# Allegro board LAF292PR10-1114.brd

Outline 301 x 98 mm; copper layers: TOP, GND1, IN1, GND2, IN2, GND3, VCC, IN3, GND4, IN4, GND5, BOTTOM. Coordinates in mm from the lower left corner of the outline.

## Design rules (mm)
net group CLK_ITPXDP_: nets CLK_ITPXDP_N CLK_ITPXDP_P
net group CLK_ITPXDP__R: nets CLK_ITPXDP_N_R CLK_ITPXDP_P_R
net group CPU_DP1_0: nets CPU_DP1_N0 CPU_DP1_P0
net group CPU_DP1_0_C: nets CPU_DP1_N0_C CPU_DP1_P0_C
net group CPU_DP1_1: nets CPU_DP1_N1 CPU_DP1_P1
net group CPU_DP1_1_C: nets CPU_DP1_N1_C CPU_DP1_P1_C
net group CPU_DP1_2: nets CPU_DP1_N2 CPU_DP1_P2
net group CPU_DP1_2_C: nets CPU_DP1_N2_C CPU_DP1_P2_C
net group CPU_DP1_3: nets CPU_DP1_N3 CPU_DP1_P3
net group CPU_DP1_3_C: nets CPU_DP1_N3_C CPU_DP1_P3_C
net group CPU_DP1_AUX: nets CPU_DP1_AUXN CPU_DP1_AUXP
net group CPU_DP1_AUX_C: nets CPU_DP1_AUXN_C CPU_DP1_AUXP_C
net group CPU_DP2_0: nets CPU_DP2_N0 CPU_DP2_P0
net group CPU_DP2_0_C: nets CPU_DP2_N0_C CPU_DP2_P0_C
net group CPU_DP2_1: nets CPU_DP2_N1 CPU_DP2_P1
net group CPU_DP2_1_C: nets CPU_DP2_N1_C CPU_DP2_P1_C
net group CPU_DP2_2: nets CPU_DP2_N2 CPU_DP2_P2
net group CPU_DP2_2_C: nets CPU_DP2_N2_C CPU_DP2_P2_C
net group CPU_DP2_3: nets CPU_DP2_N3 CPU_DP2_P3
net group CPU_DP2_3_C: nets CPU_DP2_N3_C CPU_DP2_P3_C
net group CPU_DP2_AUX: nets CPU_DP2_AUXN CPU_DP2_AUXP
net group CPU_DP2_AUX_C: nets CPU_DP2_AUXN_C CPU_DP2_AUXP_C
net group CPU_DP3_AUX: nets CPU_DP3_AUXN CPU_DP3_AUXP
net group DP_GT_SENSE: nets VCC_GT_SENSE VSS_GT_SENSE
net group EDP_AUX: nets EDP_AUXN EDP_AUXP
net group EDP_TX0: nets EDP_TXN0 EDP_TXP0
net group EDP_TX1: nets EDP_TXN1 EDP_TXP1
net group EDP_TX2: nets EDP_TXN2 EDP_TXP2
net group EDP_TX3: nets EDP_TXN3 EDP_TXP3
net group HDA-30: nets HDA_BIT_CLK HDA_BIT_CLK_R
net group HDMI_CLK: nets HDMI_CLKN HDMI_CLKP
net group HDMI_L_CLK: nets HDMI_L_CLKN HDMI_L_CLKP
net group HDMI_L_TX_0: nets HDMI_L_TX_N0 HDMI_L_TX_P0
net group HDMI_L_TX_1: nets HDMI_L_TX_N1 HDMI_L_TX_P1
net group HDMI_L_TX_2: nets HDMI_L_TX_N2 HDMI_L_TX_P2
net group HDMI_TX_0: nets HDMI_TX_N0 HDMI_TX_P0
net group HDMI_TX_1: nets HDMI_TX_N1 HDMI_TX_P1
net group HDMI_TX_2: nets HDMI_TX_N2 HDMI_TX_P2
net group INT_SPK_L: nets INT_SPK_L+ INT_SPK_L-
net group INT_SPK_R: nets INT_SPK_R+ INT_SPK_R-
net group INT_SPKR_L: nets INT_SPKR_L+ INT_SPKR_L-
net group INT_SPKR_R: nets INT_SPKR_R+ INT_SPKR_R-
net group PCIE_PRX_DTX_5: nets PCIE_PRX_DTX_N5 PCIE_PRX_DTX_P5
net group PCIE_PRX_DTX_7: nets PCIE_PRX_DTX_N7 PCIE_PRX_DTX_P7
net group PCIE_PRX_DTX_8: nets PCIE_PRX_DTX_N8 PCIE_PRX_DTX_P8
net group PCIE_PRX_DTX_9: nets PCIE_PRX_DTX_N9 PCIE_PRX_DTX_P9
net group PCIE_PRX_DTX_10: nets PCIE_PRX_DTX_N10 PCIE_PRX_DTX_P10
net group PCIE_PRX_DTX_11: nets PCIE_PRX_DTX_N11 PCIE_PRX_DTX_P11
net group PCIE_PRX_DTX_12: nets PCIE_PRX_DTX_N12 PCIE_PRX_DTX_P12
net group PCIE_PRX_L_DTX_7: nets PCIE_PRX_L_DTX_N7 PCIE_PRX_L_DTX_P7
net group PCIE_PRX_SW_DTX_7: nets PCIE_PRX_SW_DTX_N7 PCIE_PRX_SW_DTX_P7
net group PCIE_PTX_DRX_5: nets PCIE_PTX_DRX_N5 PCIE_PTX_DRX_P5
net group PCIE_PTX_DRX_7: nets PCIE_PTX_DRX_N7 PCIE_PTX_DRX_P7
net group PCIE_PTX_DRX_8: nets PCIE_PTX_DRX_N8 PCIE_PTX_DRX_P8
net group PCIE_PTX_DRX_9: nets PCIE_PTX_DRX_N9 PCIE_PTX_DRX_P9
net group PCIE_PTX_DRX_10: nets PCIE_PTX_DRX_N10 PCIE_PTX_DRX_P10
net group PCIE_PTX_DRX_11: nets PCIE_PTX_DRX_N11 PCIE_PTX_DRX_P11
net group PCIE_PTX_DRX_12: nets PCIE_PTX_DRX_N12 PCIE_PTX_DRX_P12
net group PCIE_PTX_L_DRX_7: nets PCIE_PTX_L_DRX_N7 PCIE_PTX_L_DRX_P7
net group REM_DIODE1: nets REM_DIODE1_N REM_DIODE1_P
net group SD/MMCDAT0/RCLK+: nets SD/MMCDAT0/RCLK+ SD/MMCDAT1/RCLK-
net group SD/MMCDAT0/RCLK+-R: nets SD/MMCDAT0/RCLK+_R SD/MMCDAT1/RCLK-_R
net group SD_UHS2_D0: nets SD_UHS2_D0N SD_UHS2_D0P
net group SD_UHS2_D1: nets SD_UHS2_D1N SD_UHS2_D1P
net group TBTA_AUX: nets TBTA_AUXN TBTA_AUXP
net group TBTA_AUX_C: nets TBTA_AUXN_C TBTA_AUXP_C
net group TBTA_BOT_: nets TBTA_BOT_N TBTA_BOT_P
net group TBTA_BOT__R: nets TBTA_BOT_N_R TBTA_BOT_P_R
net group TBTA_TOP_: nets TBTA_TOP_N TBTA_TOP_P
net group TBTA_TOP__R: nets TBTA_TOP_N_R TBTA_TOP_P_R
net group TBTA_USB20_: nets TBTA_USB20_N TBTA_USB20_P
net group TBTB_AUX: nets TBTB_AUXN TBTB_AUXP
net group TBTB_AUX_C: nets TBTB_AUXN_C TBTB_AUXP_C
net group TBTB_BOT_: nets TBTB_BOT_N TBTB_BOT_P
net group TBTB_BOT__R: nets TBTB_BOT_N_R TBTB_BOT_P_R
net group TBTB_TOP_: nets TBTB_TOP_N TBTB_TOP_P
net group TBTB_TOP__R: nets TBTB_TOP_N_R TBTB_TOP_P_R
net group TBTB_USB20_: nets TBTB_USB20_N TBTB_USB20_P
net group USB2.0-3: nets USB20_N3 USB20_P3
net group USB3_PRX_C_DTX_N4: nets USB3_PRX_C_DTX_N4 USB3_PRX_DTX_N4
net group USB3_PRX_C_DTX_P4: nets USB3_PRX_C_DTX_P4 USB3_PRX_DTX_P4
net group USB3_PRX_DTX_1: nets USB3_PRX_DTX_N1 USB3_PRX_DTX_P1
net group USB3_PRX_DTX_2: nets USB3_PRX_DTX_N2 USB3_PRX_DTX_P2
net group USB3_PRX_DTX_3: nets USB3_PRX_DTX_N3 USB3_PRX_DTX_P3
net group USB3_PTX_C_DRX_1: nets USB3_PTX_C_DRX_N1 USB3_PTX_C_DRX_P1
net group USB3_PTX_C_DRX_2: nets USB3_PTX_C_DRX_N2 USB3_PTX_C_DRX_P2
net group USB3_PTX_C_DRX_3: nets USB3_PTX_C_DRX_N3 USB3_PTX_C_DRX_P3
net group USB3_PTX_C_DRX_4: nets USB3_PTX_C_DRX_N4 USB3_PTX_C_DRX_P4
net group USB3_PTX_DRX_1: nets USB3_PTX_DRX_N1 USB3_PTX_DRX_P1
net group USB3_PTX_DRX_2: nets USB3_PTX_DRX_N2 USB3_PTX_DRX_P2
net group USB3_PTX_DRX_3: nets USB3_PTX_DRX_N3 USB3_PTX_DRX_P3
net group USB3_PTX_DRX_4: nets USB3_PTX_DRX_N4 USB3_PTX_DRX_P4
net group USB20_1: nets USB20_N1 USB20_P1
net group USB20_2: nets USB20_N2 USB20_P2
net group USB20_2_R: nets USB20_N2_R USB20_P2_R
net group USB20_4: nets USB20_N4 USB20_P4
net group USB20_4_L: nets USB20_N4_L USB20_P4_L
net group USB20_5: nets USB20_N5 USB20_P5
net group USB20_5_R: nets USB20_N5_R USB20_P5_R
net group USB20_6: nets USB20_N6 USB20_P6
net group USB20_6_R: nets USB20_N6_R USB20_P6_R
net group USB20_7: nets USB20_N7 USB20_P7
net group USB20_7_L: nets USB20_N7_L USB20_P7_L
net group USB20_8: nets USB20_N8 USB20_P8
net group USB20_8_R: nets USB20_N8_R USB20_P8_R
net group USB20_10: nets USB20_N10 USB20_P10
net group W10S10: nets AUD_HP_NB_SENSE AUD_SENSE_A
net group 5: nets BC_DAT_ECE1117 CPU_DP1_CTRL_DATA CPU_DP2_CTRL_DATA DDR_XDP_WAN_SMBDAT ESPI_IO0 ESPI_IO0_R ESPI_IO1 ESPI_IO1_R ESPI_IO2 ESPI_IO2_R ESPI_IO3 ESPI_IO3_R I2C1_SDA_TP ISH_I2C0_SDA ISH_I2C1_SDA ISH_I2C2_SDA MEM_SMBDATA PBAT_SMBDAT_C PCH_SPI_CS#0 PCH_SPI_CS#0_R1 PCH_SPI_CS#0_R2 PCH_SPI_CS#1 PCH_SPI_CS#1_R1 PCH_SPI_CS#1_R2 PCH_SPI_CS#2 PCH_SPI_CS#2_R PCH_SPI_D0 PCH_SPI_D0_2_R PCH_SPI_D0_R1 PCH_SPI_D1 PCH_SPI_D1_2_R PCH_SPI_D1_R1 PCH_SPI_D2 PCH_SPI_D2_R1 PCH_SPI_D3 PCH_SPI_D3_R1 PCH_SPI_DO2_XDP PCH_SPI_DO_XDP SML0_SMBDATA SML1_SMBDATA TBT_I2C_SDA TBT_ROM_CS# TBT_ROM_DI TBT_ROM_DO UPD1_SMBDAT UPD1_SMBUS_DAT_Q UPD2_SMBDAT UPD2_SMBUS_DAT_Q
net group 10: nets AUD_HP_OUT_L AUD_HP_OUT_L1 AUD_HP_OUT_R AUD_HP_OUT_R1 BC_CLK_ECE1117 CFG0 CLK_TP_SIO_I2C_DAT CPU_DP1_CTRL_CLK CPU_DP2_CTRL_CLK DAT_TP_SIO_I2C_CLK DAT_TP_SIO_R DDR_XDP_WAN_SMBCLK ESPI_CLK H_CATERR# H_THERMTRIP# H_VCCST_PWRGD_XDP HDMI_CTRL_CLK INTRUDER# ISH_I2C0_SCL ISH_I2C1_SCL ISH_I2C2_SCL MEM_SMBCLK N39469972 PBAT_SMBCLK_C PCH_DPWROK PCH_PCIE_WAKE# PCH_PLTRST# PCH_PLTRST#_EC PCH_RSMRST# PCH_RTCRST# PCH_SPI_CLK PCH_SPI_CLK_2_R PCH_SPI_CLK_R1 PCIE_WAKE# PCIE_WAKE#_R PLTRST_TPM# RESET_OUT#_R SIO_PWRBTN# SML0_SMBCLK SML1_SMBCLK SRTCRST# SUSCLK_R SYS_RESET# SYS_RESET#_R TBT_I2C_SCL TBT_ROM_CLK TBTA_ROM_CLK_PD TS_I2C_SCL UPD1_SMBCLK UPD1_SMBUS_CLK_Q UPD2_SMBCLK UPD2_SMBUS_CLK_Q VCCST_PWRGD VCCST_PWRGD_CPU VCCST_PWRGD_EC XDP_OBS0 XDP_OBS0_R XDP_OBS1 XDP_OBS1_R
net group 12: nets CPU_XDP_TDI CPU_XDP_TDO CPU_XDP_TMS H_CPU_SVIDALRT# PCH_JTAG_TDI PCH_JTAG_TDO PCH_JTAG_TMS PCH_RSMRST#_AND PECI_EC PECI_EC_R SD/MMCCD# SD/MMCCLK SD/MMCCLK_R SD/MMCCMD SD/MMCDAT2 SD/MMCDAT2_R SD/MMCDAT3 SD/MMCDAT3_R SDWP TDI_XDP TDO_XDP VIDALERT_N VIDALERT_N_B VIDSCLK VIDSCLK_B VIDSOUT VIDSOUT_B XDP_JTAGX XDP_TMS
net group 15: nets PCH_RTCX2 PCH_RTCX2_R RTCRST_ON WIGIG_32KHZ
net group 20: nets CPU_XDP_TCLK MSCLK PCH_JTAG_TCK PCH_RTCX1 PCI_CLK_LPC1 SUSCLK XCLK_BIASREF XTAL_25_IN XTAL_25_OUT XTAL_25_OUT_R
net group 25: nets N28769860 VCCIO_SENSE VCCSENSE VSSIO_SENSE
net group 90H-TBT: nets TBTA_RX1N TBTA_RX1P TBTA_RX2N TBTA_RX2P TBTA_TX1N TBTA_TX1N_C TBTA_TX1P TBTA_TX1P_C TBTA_TX2N TBTA_TX2N_C TBTA_TX2P TBTA_TX2P_C TBTB_RX1N TBTB_RX1P TBTB_RX2N TBTB_RX2P TBTB_TX1N TBTB_TX1N_C TBTB_TX1P TBTB_TX1P_C TBTB_TX2N TBTB_TX2N_C TBTB_TX2P TBTB_TX2P_C
net group AR DP: nets TBTA_LSRX TBTA_LSRX_R TBTA_LSTX TBTA_LSTX_R TBTA_SBU1 TBTA_SBU1_R TBTA_SBU2 TBTA_SBU2_R TBTB_LSRX TBTB_LSRX_R TBTB_LSTX TBTB_LSTX_R TBTB_SBU1 TBTB_SBU1_R TBTB_SBU2 TBTB_SBU2_R
net group AR HDMI: nets AR_DP1_N0 AR_DP1_N1 AR_DP1_N2 AR_DP1_N3 AR_DP1_P0 AR_DP1_P1 AR_DP1_P2 AR_DP1_P3
net group ASYNCHRONOUS: nets +DDR_VREF_B_DQ CFG_RCOMP EDRAM_OPIO_RCOMP USBCOMP
net group CARD READER-RTS5250: nets SD/MMCCMD_R
net group CLK-PCIE-12-30: nets CLK_PCIE_N0 CLK_PCIE_N1 CLK_PCIE_N3 CLK_PCIE_N5 CLK_PCIE_P0 CLK_PCIE_P1 CLK_PCIE_P3 CLK_PCIE_P5
net group CODEC: nets HP_OUT_L HP_OUT_R LINE1_L LINE1_R
net group CONTROL LINK SIGNAL: nets PCH_CL_CLK1 PCH_CL_DATA1 PCH_CL_RST1#
net group DDRA_DQS0: nets DDR_A_D0 DDR_A_D1 DDR_A_D2 DDR_A_D3 DDR_A_D4 DDR_A_D5 DDR_A_D6 DDR_A_D7 DDR_A_DQS0 DDR_A_DQS#0
net group DDRA_DQS1: nets DDR_A_D8 DDR_A_D9 DDR_A_D10 DDR_A_D11 DDR_A_D12 DDR_A_D13 DDR_A_D14 DDR_A_D15 DDR_A_DQS1 DDR_A_DQS#1
net group DDRA_DQS2: nets DDR_A_D16 DDR_A_D17 DDR_A_D18 DDR_A_D19 DDR_A_D20 DDR_A_D21 DDR_A_D22 DDR_A_D23 DDR_A_DQS2 DDR_A_DQS#2
net group DDRA_DQS3: nets DDR_A_D24 DDR_A_D25 DDR_A_D26 DDR_A_D27 DDR_A_D28 DDR_A_D29 DDR_A_D30 DDR_A_D31 DDR_A_DQS3 DDR_A_DQS#3
net group DDRA_DQS4: nets DDR_A_D32 DDR_A_D33 DDR_A_D34 DDR_A_D35 DDR_A_D36 DDR_A_D37 DDR_A_D38 DDR_A_D39 DDR_A_DQS4 DDR_A_DQS#4
net group DDRA_DQS5: nets DDR_A_D40 DDR_A_D41 DDR_A_D42 DDR_A_D43 DDR_A_D44 DDR_A_D45 DDR_A_D46 DDR_A_D47 DDR_A_DQS5 DDR_A_DQS#5
net group DDRA_DQS6: nets DDR_A_D48 DDR_A_D49 DDR_A_D50 DDR_A_D51 DDR_A_D52 DDR_A_D53 DDR_A_D54 DDR_A_D55 DDR_A_DQS6 DDR_A_DQS#6
net group DDRA_DQS7: nets DDR_A_D56 DDR_A_D57 DDR_A_D58 DDR_A_D59 DDR_A_D60 DDR_A_D61 DDR_A_D62 DDR_A_D63 DDR_A_DQS7 DDR_A_DQS#7
net group DDRB_DQS0: nets DDR_B_D0 DDR_B_D1 DDR_B_D2 DDR_B_D3 DDR_B_D4 DDR_B_D5 DDR_B_D6 DDR_B_D7 DDR_B_DQS0 DDR_B_DQS#0
net group DDRB_DQS1: nets DDR_B_D8 DDR_B_D9 DDR_B_D10 DDR_B_D11 DDR_B_D12 DDR_B_D13 DDR_B_D14 DDR_B_D15 DDR_B_DQS1 DDR_B_DQS#1
net group DDRB_DQS2: nets DDR_B_D16 DDR_B_D17 DDR_B_D18 DDR_B_D19 DDR_B_D20 DDR_B_D21 DDR_B_D22 DDR_B_D23 DDR_B_DQS2 DDR_B_DQS#2
net group DDRB_DQS3: nets DDR_B_D24 DDR_B_D25 DDR_B_D26 DDR_B_D27 DDR_B_D28 DDR_B_D29 DDR_B_D30 DDR_B_D31 DDR_B_DQS3 DDR_B_DQS#3
net group DDRB_DQS4: nets DDR_B_D32 DDR_B_D33 DDR_B_D34 DDR_B_D35 DDR_B_D36 DDR_B_D37 DDR_B_D38 DDR_B_D39 DDR_B_DQS4 DDR_B_DQS#4
net group DDRB_DQS5: nets DDR_B_D40 DDR_B_D41 DDR_B_D42 DDR_B_D43 DDR_B_D44 DDR_B_D45 DDR_B_D46 DDR_B_D47 DDR_B_DQS5 DDR_B_DQS#5
net group DDRB_DQS6: nets DDR_B_D48 DDR_B_D49 DDR_B_D50 DDR_B_D51 DDR_B_D52 DDR_B_D53 DDR_B_D54 DDR_B_D55 DDR_B_DQS6 DDR_B_DQS#6
net group DDRB_DQS7: nets DDR_B_D56 DDR_B_D57 DDR_B_D58 DDR_B_D59 DDR_B_D60 DDR_B_D61 DDR_B_D62 DDR_B_D63 DDR_B_DQS7 DDR_B_DQS#7
net group EDP: nets EDP_AUXN_C EDP_AUXP_C EDP_TXN0_C EDP_TXN1_C EDP_TXN2_C EDP_TXN3_C EDP_TXP0_C EDP_TXP1_C EDP_TXP2_C EDP_TXP3_C
net group ESPI-30: nets ESPI_CLK_5105
net group GREENCLK & XTAL: nets MEC_XTAL1 MEC_XTAL2 MEC_XTAL2_R
net group HDA-5-15: nets DMIC0 DMIC_CLK0 DMIC_CLK_CODEC HDA_RST# HDA_RST#_R HDA_SDIN0 HDA_SDIN0_R HDA_SDOUT HDA_SDOUT_R HDA_SYNC HDA_SYNC_R
net group I2C: nets ACC1_I2C0_SCL ACC1_I2C0_SDA ALS_I2C0_SCL ALS_I2C0_SDA I2C1_SDA_TP_R ISH_I2C2_SCL_R ISH_I2C2_SDA_R SAR_I2C0_SCL SAR_I2C0_SDA
net group OTHERS SINGLE-END: nets BAT1_LED# BAT2_LED# BATT_YELLOW#
net group PCIE: nets PCIE_PRX_C_DTX_N1 PCIE_PRX_C_DTX_N2 PCIE_PRX_C_DTX_N3 PCIE_PRX_C_DTX_N4 PCIE_PRX_C_DTX_P1 PCIE_PRX_C_DTX_P2 PCIE_PRX_C_DTX_P3 PCIE_PRX_C_DTX_P4 PCIE_PRX_DTX_N1 PCIE_PRX_DTX_N2 PCIE_PRX_DTX_N3 PCIE_PRX_DTX_N4 PCIE_PRX_DTX_P1 PCIE_PRX_DTX_P2 PCIE_PRX_DTX_P3 PCIE_PRX_DTX_P4 PCIE_PTX_C_DRX_N1 PCIE_PTX_C_DRX_N2 PCIE_PTX_C_DRX_N3 PCIE_PTX_C_DRX_N4 PCIE_PTX_C_DRX_N5 PCIE_PTX_C_DRX_N8 PCIE_PTX_C_DRX_N9 PCIE_PTX_C_DRX_N10 PCIE_PTX_C_DRX_N11 PCIE_PTX_C_DRX_N12 PCIE_PTX_C_DRX_P1 PCIE_PTX_C_DRX_P2 PCIE_PTX_C_DRX_P3 PCIE_PTX_C_DRX_P4 PCIE_PTX_C_DRX_P5 PCIE_PTX_C_DRX_P8 PCIE_PTX_C_DRX_P9 PCIE_PTX_C_DRX_P10 PCIE_PTX_C_DRX_P11 PCIE_PTX_C_DRX_P12 PCIE_PTX_C_SW_DRX_N7 PCIE_PTX_C_SW_DRX_P7 PCIE_PTX_DRX_N1 PCIE_PTX_DRX_N2 PCIE_PTX_DRX_N3 PCIE_PTX_DRX_N4 PCIE_PTX_DRX_P1 PCIE_PTX_DRX_P2 PCIE_PTX_DRX_P3 PCIE_PTX_DRX_P4 PCIE_PTX_SW_DRX_N7 PCIE_PTX_SW_DRX_P7
net group PLATFORM CLK: nets CLKREQ_PCIE#0 CLKREQ_PCIE#1 CLKREQ_PCIE#3 CLKREQ_PCIE#5
net group PWR: nets +3.3V_VDD_PIC +5V_RUN ACIN_ISL9538 ADP_ISL9538 I_ADP N16400770 N20151644 N22406932 N27077001 N132005053
net group SIM: nets UIM_CLK UIM_DATA UIM_RESET
net group SINGLE-END CLOCK: nets JTAG_CLK
net group THERMAL: nets REM_DIODE2_N REM_DIODE2_P REM_DIODE4_N REM_DIODE4_P
net group USB 2.0: nets PD1_USB20_N PD1_USB20_P PD2_USB20_N PD2_USB20_P SW_USB20_N9 SW_USB20_P9 USB20_N9 USB20_N9_R USB20_P9 USB20_P9_R
net group VIA-30: nets +TBTB_VBUS_1
net group VIA-40: nets 3V_VIN 5V_VIN +CHARGER_SRC BST_3V CPU_B+ GPU_B+ LG1_ISL9538 LG2_ISL9538 LX1_ISL9538 LX2_ISL9538 LX_3V SA_SW UG1_ISL9538 UG2_ISL9538 VCCSA_B+
net group VSSSENSE: nets VSSSENSE
net group W15: nets CPU_POPIRCOMP EMMC_RCOMP EOPIO_RCOMP PCH_POPIRCOMP PCIE_RCOMPN PCIE_RCOMPP SD_RCOMP SM_RCOMP0 SM_RCOMP1 SM_RCOMP2
net group W20: nets +0.6V_DDR_VTT +0.6VSP +0.9V_TBT_CIO +0.9V_TBT_DP +0.9V_TBT_LVR_OUT +0.9V_TBT_PCIE +0.9V_TBT_USB +1.0V_AMPHYPLL +1.0V_APLL +1.0V_APLLEBB +1.0V_CLK1 +1.0V_CLK2 +1.0V_CLK3 +1.0V_CLK4 +1.0V_CLK5 +1.0V_CLK6 +1.0V_DTS +1.0V_MPHYAON +1.0V_PRIM_COREP +1.0V_PRIM_XDP +1.0V_SRAM +1.0V_VCCST +1.0V_VCCST_C +1.0V_VCCSTG +1.0V_VCCSTG_C +1.0V_VCCSTG_R +1.0VO_DSW +1.0VS_VCCIO +1.2V_DDR_B+ +1.2V_DDRP +1.2V_LDO +1.2V_MEM_CPUCLK +1.8V_3.3V_ALW_VTR3 +1.8V_MEM +1.8V_PGPPF +1.8V_PRIM +1.8V_RUN +1.8V_RUN_AUDIO +1.8V_RUN_CARD +1.8V_RUN_UZ8 +1.8V_VIN +1.8VALWP +1VALWP +1VALWP_B+ +1VS_VCCIOP +3.3V_1.8V_ESPI +3.3V_1.8V_PGPPA +3.3V_1.8V_PGPPG +3.3V_ALW2 +3.3V_ALW_DSW +3.3V_ALW_DSW_R +3.3V_ALW_PCH_UZ3 +3.3V_ALW_UZ12 +3.3V_ALWP +3.3V_CAM +3.3V_EC_PLL +3.3V_HDD_M2 +3.3V_MMI_IN +3.3V_PDA_VOUT +3.3V_PDB_VOUT +3.3V_PGPPB +3.3V_PGPPC +3.3V_PGPPD +3.3V_PGPPE +3.3V_RTC_LDO +3.3V_RUN_AUDIO +3.3V_RUN_AUDIO_DVDD +3.3V_RUN_AUDIO_IO +3.3V_RUN_AUDIO_UZ5 +3.3V_RUN_CARD +3.3V_RUN_UZ3 +3.3V_SPI +3.3V_TBT +3.3V_TBT_FLASH_R +3.3V_TBT_LC +3.3V_TBT_S0 +3.3V_TBT_SX +3.3V_TBTB_FLASH +3.3V_TP +3.3V_TSP +3.3V_TSP_UZ41 +3.3V_VCCHDA +3.3V_VDD_PIC_PDA +3.3V_VDD_PIC_PDB +3.3V_WLAN_UZ2 +3.3V_WWAN_AUX +3.3V_WWAN_MAIN +3.3V_WWAN_UZ4 +5V_ALW2 +5V_ALW_PDB +5V_ALWP +5V_PD_VDD +5V_RUN_AUDIO +5V_RUN_AUDIO_UZ5 +5V_RUN_PVDD_L +5V_RUN_UZ4 +5V_TBT_VBUS +5V_TBTA_VBUS_D +5V_TBTB_VBUS_D +5V_USB_CHG_PWR +BL_PWR_SRC +COINCELL +DCPRTC +DDR_VREF_A_DQ +DDR_VREF_CA +DV_12S +EC_DEBUG_VCC +EDP_VDD +LCDVDD +MIC2-VREFO-L +MIC2-VREFO-R +PBATT +PECI_VREF +PWR_SRC +PWR_SRC_AC +PWR_SRC_R +RREF +RTC_CELL +RTC_CELL_PCH +RTC_CELL_VBAT +SD40_AV12 +SDREG2 +SIM_PWR +TBT_SVR_IND +TBTA_LDO_BMC +TBTA_SENSE +TBTA_VBUS_1 +TBTB_LDO_BMC +TBTB_SENSE +USB_EX2_PWR +UZ12_TPM +UZ12_VHIO +VCC1V8A_TBTA_LDO +VCC1V8A_TBTB_LDO +VCC1V8D_TBTA_LDO +VCC1V8D_TBTB_LDO +VCC3V3_ANA_PCIE +VCC3V3_ANA_USB2 +VCC_1P8 +VCC_CORE_G0 +VCC_CORE_G1 +VCC_GT +VCC_GT_+VCC_CORE +VCC_SA +VCC_SFR_OC +VCHGR +VDD_IO +VDDA_AVDD1 +VHDMI_VCC +VR_CAP +VREFCA +VREFDQ_A +VREFDQ_B +VSS_PLL +Z4012 EDP_COMP N23412536 N23415795 N23718631
net group W50: nets RING2 RING2_R SLEEVE SLEEVE_R
nets with their own width: min track width 0.127; nets GND
nets with their own width: min track width 0.254; nets +AC1_IN +AC2_IN N17419094 N17419103 N17419127 N17419137 N19725601 N22211458 N22242716 N22400408 N22440950 N35029420 N44737537 N49118067
nets with their own width: min track width 0.508; nets +1.0V_MPHYGT +1.0V_PRIM +1.0V_PRIM_CORE +3.3V_ALW +3.3V_ALW_UE1 +3.3V_TBTA_FLASH +3.3V_WWAN +VCC_CORE GNDA GT_SNUB VCC_GT
nets with their own width: min track width 1.524; nets +1.2V_MEM

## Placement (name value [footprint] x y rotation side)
CA1  680P_0402_50V7K  [C_0402]  280.59 36.03 90 top
CA2  330P_0402_50V7K  [C_0402]  279.44 32.01 90 top
CA3  330P_0402_50V7K  [C_0402]  279.44 34.17 90 top
CA4  680P_0402_50V7K  [C_0402]  278.88 41.61 180 top
CA5  100P_0201_50V8J  [C_0201]  230.44 36.64 180 bottom
CA6  100P_0201_50V8J  [C_0201]  229.24 36.65 180 bottom
CA7  0.1U_0201_10V6K  [C_0201]  225.9 38.08 90 top
CA8  0.1U_0201_10V6K  [C_0201]  270.39 40.44 180 top
CA9  10U_0603_10V6M  [C_0603]  270.03 41.27 90 top
CA10  0.1U_0201_10V6K  [C_0201]  262.07 37.22 270 top
CA12  680P_0402_50V7K  [C_0402]  281.47 36.94 270 top
CA13  680P_0402_50V7K  [C_0402]  279.82 42.58 270 top
CA19  1000P_0402_50V7K  [C_0402]  298.32 23.45 180 top
CA22  1000P_0402_50V7K  [C_0402]  289.96 24.9 90 top
CA23  1000P_0402_50V7K  [C_0402]  289.98 23.12 90 top
CA24  1000P_0402_50V7K  [C_0402]  298.32 22.56 180 top
CA25  10U_0603_10V6M  [C_0603]  272.56 34.75 0 top
CA27  0.1U_0402_25V6  [C_0402]  273.35 36.7 180 top
CA28  0.1U_0402_25V6  [C_0402]  273.35 35.81 180 top
CA29  1U_0603_10V6K  [C_0603]  270.09 29.9 270 top
CA31  1U_0603_10V6K  [C_0603]  259.96 38.12 90 top
CA33  10P_0402_50V8J  [C_0402]  259.81 34.93 180 top
CA35  2.2U_0402_6.3V6M  [C_0402]  273.33 40.56 90 top
CA41  0.1U_0402_25V6  [C_0402]  261.88 40.06 180 top
CA43  10U_0603_10V6M  [C_0603]  272.51 39.11 0 top
CA44  10U_0603_10V6M  [C_0603]  272.51 37.77 0 top
CA45  0.1U_0201_10V6K  [C_0201]  268.47 40.44 0 top
CA46  10U_0603_10V6M  [C_0603]  268.76 41.27 90 top
CA47  0.1U_0201_10V6K  [C_0201]  264.75 40.22 180 top
CA48  10U_0603_10V6M  [C_0603]  267.51 41.3 90 top
CA49  1U_0603_10V6K  [C_0603]  271.36 29.9 270 top
CA51  10U_0603_10V6M  [C_0603]  271.95 41.42 90 top
CA52  10U_0603_10V6M  [C_0603]  267.43 29.9 270 top
CA53  10U_0603_10V6M  [C_0603]  261.84 29.84 270 top
CA54  10P_0402_50V8J  [C_0402]  259.8 35.84 180 top
CA55  0.1U_0201_10V6K  [C_0201]  262.09 30.94 90 top
CA56  10U_0603_10V6M  [C_0603]  261.27 31.23 180 top
CA57  0.1U_0201_10V6K  [C_0201]  265.87 30.09 0 top
CA58  10U_0603_10V6M  [C_0603]  268.7 29.9 270 top
CA59  10U_0603_10V6M  [C_0603]  253.6 39.33 180 top
CA60  0.1U_0201_10V6K  [C_0201]  270.55 46.02 90 top
CA61  10U_0603_10V6M  [C_0603]  261.24 36.92 180 top
CA62  100P_0402_50V8J  [C_0402]  275.76 34.91 270 top
CA63  12P_0402_50V8J  [C_0402]  254.55 39.12 90 top
CA64  68P_0402_50V8J  [C_0402]  256.1 38.11 90 top
CA65  12P_0402_50V8J  [C_0402]  263.82 28.44 180 top
CA66  68P_0402_50V8J  [C_0402]  263.82 29.39 180 top
CA67  12P_0402_50V8J  [C_0402]  259.81 29.28 270 top
CA68  68P_0402_50V8J  [C_0402]  260.76 29.28 270 top
CA69  33P_0402_50V8J  [C_0402]  266.03 29.34 270 top
CA72  100P_0402_50V8J  [C_0402]  275.74 37.63 90 top
CA73  330P_0402_50V8J  [C_0402]  274.82 37.51 90 top
CA74  330P_0402_50V8J  [C_0402]  274.81 39.57 0 top
CC7  33P_0402_50V8J  [C_0402]  169.46 51.19 90 bottom
CC8  33P_0402_50V8J  [C_0402]  178.43 58.59 270 top
CC9  0.1U_0201_10V6K  [C_0201]  169.9 63.66 270 bottom
CC10  0.1U_0201_10V6K  [C_0201]  169.89 60.5 90 bottom
CC21  15P_0402_50V8J  [C_0402]  129.84 90.51 270 bottom
CC22  15P_0402_50V8J  [C_0402]  129.84 91.4 90 bottom
CC23  15P_0402_50V8J  [C_0402]  158.81 63.66 0 top
CC24  1U_0402_6.3V6K  [C_0402]  145.25 54.44 270 top
CC25  1U_0402_6.3V6K  [C_0402]  165.05 44.63 0 top
CC26  12P_0402_50V8J  [C_0402]  160.58 63.68 0 top
CC27  47P_0402_50V8J  [C_0402]  146.47 48.98 180 bottom
CC28  0.1U_0201_10V6K  [C_0201]  63.57 92.19 180 bottom
CC29  0.1U_0201_10V6K  [C_0201]  63.58 89.49 180 bottom
CC30  0.1U_0201_10V6K  [C_0201]  86.25 85.84 0 top
CC32  0.1U_0402_25V6  [C_0402]  63.21 86.49 270 top
CC33  0.1U_0402_25V6  [C_0402]  62.2 92.02 270 bottom
CC176  10U_0402_6.3V6M  [C_0402]  133.95 54.26 270 top
CC177  10U_0402_6.3V6M  [C_0402]  131.41 54.14 270 top
CC178  10U_0402_6.3V6M  [C_0402]  140.42 54.26 270 top
CC179  10U_0402_6.3V6M  [C_0402]  138.9 54.26 270 top
CC195  1U_0402_6.3V6K  [C_0402]  147.36 79.03 270 top
CC199  1U_0402_6.3V6K  [C_0402]  133.61 87.46 180 top
CC202  1U_0402_6.3V6K  [C_0402]  143.17 75.52 180 top
CC203  1U_0402_6.3V6K  [C_0402]  147.02 75.4 90 top
CC204  1U_0402_6.3V6K  [C_0402]  156.22 66 0 top
CC205  1U_0402_6.3V6K  [C_0402]  144.36 71.46 270 top
CC206  1U_0402_6.3V6K  [C_0402]  146.27 71.97 180 top
CC207  1U_0402_6.3V6K  [C_0402]  147.31 69.69 180 top
CC208  1U_0402_6.3V6K  [C_0402]  147.08 71.33 0 top
CC209  1U_0402_6.3V6K  [C_0402]  145.33 70.58 0 top
CC210  47U_0805_6.3V6M  [C_0805]  156.05 89.2 270 top
CC211  1U_0402_6.3V6K  [C_0402]  147.05 73.06 0 top
CC212  1U_0402_6.3V6K  [C_0402]  156.05 70.19 270 top
CC213  1U_0402_6.3V6K  [C_0402]  151.73 52.49 270 top
CC214  0.1U_0201_10V6K  [C_0201]  153.25 54.57 270 top
CC215  1U_0402_6.3V6K  [C_0402]  143.8 66.14 180 top
CC216  1U_0402_6.3V6K  [C_0402]  158.24 78.99 270 top
CC217  1U_0402_6.3V6K  [C_0402]  144.44 69.64 180 top
CC218  1U_0402_6.3V6K  [C_0402]  146.14 74.51 0 top
CC219  47U_0805_6.3V6M  [C_0805]  151.06 87.93 180 top
CC220  47U_0805_6.3V6M  [C_0805]  146.42 87.58 90 top
CC221  47U_0805_6.3V6M  [C_0805]  138.88 87.85 0 top
CC222  1U_0402_6.3V6K  [C_0402]  150.28 71.24 180 top
CC223  0.1U_0201_10V6K  [C_0201]  146.47 66.04 270 top
CC224  1U_0402_6.3V6K  [C_0402]  145.08 66.07 270 top
CC225  47U_0805_6.3V6M  [C_0805]  144.72 87.58 90 top
CC226  47U_0805_6.3V6M  [C_0805]  142.13 87.58 90 top
CC250  1U_0402_6.3V6K  [C_0402]  133 65.29 90 top
CC251  1U_0402_6.3V6K  [C_0402]  139.44 66.89 90 top
CC252  1U_0402_6.3V6K  [C_0402]  138.55 66.89 90 top
CC253  1U_0402_6.3V6K  [C_0402]  132.11 65.29 90 top
CC264  1U_0402_6.3V6K  [C_0402]  148.9 76.19 180 top
CC265  1U_0402_6.3V6K  [C_0402]  148.7 66.84 270 top
CC266  0.01UF_0402_25V7K  [C_0402]  149.7 51.22 270 bottom
CC269  0.1U_0402_25V6  [C_0402]  65.26 91.18 180 bottom
CC270  0.1U_0201_10V6K  [C_0201]  144.1 65.24 180 top
CC279  22U_0603_6.3V6M  [C_0603]  147.62 66.82 270 top
CC280  22U_0603_6.3V6M  [C_0603]  146.64 67.98 0 top
CC281  0.1U_0201_10V6K  [C_0201]  158.71 89.02 270 top
CC288  1U_0402_6.3V6K  [C_0402]  142.65 68.42 0 top
CC294  22U_0603_6.3V6M  [C_0603]  129.38 54.25 270 top
CC295  22U_0603_6.3V6M  [C_0603]  136.74 54.25 270 top
CC296  22U_0603_6.3V6M  [C_0603]  142.2 54.25 270 top
CC297  10U_0402_6.3V6M  [C_0402]  134.96 65.68 180 top
CC300  100P_0402_50V8J  [C_0402]  104.45 83.12 180 bottom
CC301  100P_0402_50V8J  [C_0402]  109.64 86.65 270 bottom
CC302  0.1U_0402_25V6  [C_0402]  170.09 76.67 180 bottom
CC303  0.1U_0402_25V6  [C_0402]  123.49 85.86 90 bottom
CC304  0.1U_0402_25V6  [C_0402]  120.57 85.86 90 bottom
CC305  0.1U_0402_25V6  [C_0402]  117.9 87.77 90 bottom
CC306  0.1U_0402_25V6  [C_0402]  61.24 86.49 270 top
CC307  0.1U_0402_25V6  [C_0402]  66.13 92.08 270 bottom
CC308  0.1U_0402_25V6  [C_0402]  80.5 88.64 180 top
CC310  0.1U_0402_25V6  [C_0402]  104.69 86.83 180 bottom
CC312  0.1U_0402_25V6  [C_0402]  117.39 85.86 90 bottom
CC313  0.1U_0201_10V6K  [C_0201]  145.86 67.67 90 top
CC314  0.1U_0201_10V6K  [C_0201]  148.76 72.48 0 top
CC316  82P_0402_50V8J  [C_0402]  162.73 53.6 90 bottom
CC318  33P_0402_50V8J  [C_0402]  159.97 77.72 0 top
CC319  33P_0402_50V8J  [C_0402]  162.6 72.22 0 top
CC320  33P_0402_50V8J  [C_0402]  159.75 73.9 0 top
CC321  33P_0402_50V8J  [C_0402]  114.98 85.81 90 bottom
CC322  2.2P_0402_50V8C  [C_0402]  142.65 67.54 0 top
CC323  1.2P_0402_50V8C  [C_0402]  149 73.39 90 top
CC324  1.2P_0402_50V8C  [C_0402]  145.66 66.93 0 top
CC325  1.2P_0402_50V8C  [C_0402]  145.1 72.87 180 top
CC326  1U_0402_6.3V6K  [C_0402]  148.94 68.13 0 top
CC331  2.2P_0402_50V8C  [C_0402]  143.93 50.89 270 bottom
CC332  2.2P_0402_50V8C  [C_0402]  146 52.66 0 top
CC333  2.2P_0402_50V8C  [C_0402]  146.6 50.89 270 bottom
CC334  82P_0402_50V8J  [C_0402]  162.53 44.56 0 bottom
CC335  1U_0402_6.3V6K  [C_0402]  150.92 74.38 90 top
CC338  12P_0402_50V8J  [C_0402]  142.79 91.83 90 bottom
CC339  12P_0402_50V8J  [C_0402]  142.79 90.84 270 bottom
CC340  0.1U_0402_25V6K  [C_0402]  29.18 85.81 0 top
CD1  1U_0201_6.3V6K  [C_0201]  103.93 36.53 0 top
CD2  1U_0201_6.3V6K  [C_0201]  120.99 34.63 180 top
CD3  1U_0201_6.3V6K  [C_0201]  116.84 35.9 0 top
CD4  1U_0201_6.3V6K  [C_0201]  121.24 36.53 180 top
CD5  10U_0402_6.3V6M  [C_0402]  104.44 34.76 180 top
CD6  10U_0402_6.3V6M  [C_0402]  99.41 37.93 0 top
CD10  0.047U_0402_16V7K  [C_0402]  104.44 38.82 270 top
CD11  0.047U_0402_16V7K  [C_0402]  120.9 37.93 180 top
CD16  0.1U_0201_10V6K  [C_0201]  116.21 45.04 0 top
CD17  0.1U_0201_10V6K  [C_0201]  121.33 46.82 180 top
CD18  0.1U_0201_10V6K  [C_0201]  125.52 43.27 270 bottom
CD19  0.1U_0201_10V6K  [C_0201]  117.39 41.14 270 top
CD20  0.047U_0402_16V7K  [C_0402]  92.25 41.56 270 bottom
CD21  0.047U_0402_16V7K  [C_0402]  117.64 44.15 90 top
CD22  1U_0201_6.3V6K  [C_0201]  102.28 45.21 270 top
CD23  1U_0201_6.3V6K  [C_0201]  101.26 45.21 270 top
CD24  1U_0201_6.3V6K  [C_0201]  103.55 45.21 270 top
CD25  1U_0201_6.3V6K  [C_0201]  110.15 43.14 270 bottom
CD26  1U_0201_6.3V6K  [C_0201]  114.89 45.04 180 top
CD27  1U_0201_6.3V6K  [C_0201]  118.79 41.74 0 top
CD28  1U_0201_6.3V6K  [C_0201]  120.69 39.71 180 top
CD29  1U_0201_6.3V6K  [C_0201]  119.68 46.82 180 top
CD30  1U_0201_6.3V6K  [C_0201]  97.07 41.49 0 top
CD31  10U_0402_6.3V6M  [C_0402]  102.66 38.85 0 top
CD32  10U_0402_6.3V6M  [C_0402]  98.8 39.58 180 top
CD33  10U_0402_6.3V6M  [C_0402]  108.07 38.82 180 top
CD36  10U_0402_6.3V6M  [C_0402]  98.85 45.04 270 top
CD37  10U_0402_6.3V6M  [C_0402]  102.53 41.87 180 top
CD38  10U_0402_6.3V6M  [C_0402]  103.8 40.65 90 top
CD39  0.022U_0402_25V7K  [C_0402]  91.55 45.33 180 bottom
CD40  0.022U_0402_25V7K  [C_0402]  90.47 40.65 90 bottom
CD41  10U_0402_6.3V6M  [C_0402]  108.07 37.93 180 top
CD42  10U_0402_6.3V6M  [C_0402]  124.07 37.93 180 top
CD43  10U_0402_6.3V6M  [C_0402]  110.15 39.02 270 bottom
CD46  0.047U_0402_16V7K  [C_0402]  138.41 36.18 180 top
CD47  0.047U_0402_16V7K  [C_0402]  150.39 31.94 90 bottom
CD52  1U_0201_6.3V6K  [C_0201]  97.83 38.69 270 top
CD53  0.047U_0402_16V7K  [C_0402]  136.19 44.99 270 top
CD54  0.047U_0402_16V7K  [C_0402]  152.65 45.42 180 top
CD55  22U_0603_6.3V6M  [C_0603]  127.36 35.77 0 bottom
CD56  1U_0201_6.3V6K  [C_0201]  144.87 33.61 90 bottom
CD57  1U_0201_6.3V6K  [C_0201]  159.15 32.35 270 bottom
CD58  1U_0201_6.3V6K  [C_0201]  159.15 32.97 90 bottom
CD60  1U_0201_6.3V6K  [C_0201]  126.54 35.73 90 bottom
CD61  1U_0201_6.3V6K  [C_0201]  125.9 35.73 90 bottom
CD62  1U_0201_6.3V6K  [C_0201]  100.08 31.2 0 bottom
CD63  22U_0603_6.3V6M  [C_0603]  127.36 34.5 0 bottom
CD64  1U_0201_6.3V6K  [C_0201]  144.24 33.61 90 bottom
CD66  1U_0201_6.3V6K  [C_0201]  98.43 31.2 0 bottom
CD67  0.022U_0402_25V7K  [C_0402]  112.99 51.7 90 bottom
CD68  1U_0201_6.3V6K  [C_0201]  118.03 38.73 270 top
CD69  1U_0201_6.3V6K  [C_0201]  115.49 39.11 270 top
CD70  1U_0201_6.3V6K  [C_0201]  121.96 39.33 180 top
CD71  1U_0201_6.3V6K  [C_0201]  111.55 41.07 90 top
CD72  1U_0201_6.3V6K  [C_0201]  119 45.04 0 top
CD74  1U_0201_6.3V6K  [C_0201]  123.99 43.39 90 top
CD75  1U_0201_6.3V6K  [C_0201]  111.55 42.72 90 top
CD76  1U_0201_6.3V6K  [C_0201]  96.94 39.71 90 top
CD78  10U_0402_6.3V6M  [C_0402]  135.6 34.25 0 top
CD79  1U_0201_6.3V6K  [C_0201]  153.55 34.25 0 top
CD80  1U_0201_6.3V6K  [C_0201]  152.96 39.25 0 top
CD81  1U_0201_6.3V6K  [C_0201]  134.73 34.21 180 top
CD82  1U_0201_6.3V6K  [C_0201]  152.95 36.41 0 top
CD83  10U_0402_6.3V6M  [C_0402]  138.52 34.63 0 top
CD84  0.1U_0201_10V6K  [C_0201]  150.41 45.3 180 top
CD85  1U_0201_6.3V6K  [C_0201]  152.53 40.85 0 top
CD86  1U_0201_6.3V6K  [C_0201]  151.77 41.74 0 top
CD87  0.1U_0201_10V6K  [C_0201]  154.77 45.17 180 top
CD88  0.1U_0201_10V6K  [C_0201]  159.17 44.79 90 bottom
CD89  1U_0201_6.3V6K  [C_0201]  143.68 43.39 270 bottom
CD90  10U_0402_6.3V6M  [C_0402]  136.01 41.11 180 top
CD91  1U_0201_6.3V6K  [C_0201]  153.69 40.43 270 top
CD92  1U_0201_6.3V6K  [C_0201]  133.39 46.99 270 top
CD93  10U_0402_6.3V6M  [C_0402]  132.24 43.94 180 top
CD94  0.1U_0201_10V6K  [C_0201]  150.83 41.11 180 top
CD95  1U_0201_6.3V6K  [C_0201]  147.66 45.04 180 top
CD96  10U_0402_6.3V6M  [C_0402]  138.73 39.33 180 top
CD97  1U_0201_6.3V6K  [C_0201]  139.23 46.82 180 top
CD98  1U_0201_6.3V6K  [C_0201]  129.31 40.59 90 bottom
CD99  1U_0201_6.3V6K  [C_0201]  137.08 46.82 180 top
CD100  10U_0402_6.3V6M  [C_0402]  136.9 38.57 180 top
CD101  10U_0402_6.3V6M  [C_0402]  133.6 39.58 180 top
CD102  10U_0402_6.3V6M  [C_0402]  141.39 42.55 90 top
CD103  1U_0201_6.3V6K  [C_0201]  143.55 38.82 90 bottom
CD104  1U_0201_6.3V6K  [C_0201]  159.17 39.54 90 bottom
CD105  1U_0201_6.3V6K  [C_0201]  149.31 39.58 180 top
CD106  1U_0201_6.3V6K  [C_0201]  144.7 38.82 90 bottom
CD107  1U_0201_6.3V6K  [C_0201]  159.16 42.69 90 bottom
CD108  1U_0201_6.3V6K  [C_0201]  154.92 39.25 0 top
CD109  1U_0201_6.3V6K  [C_0201]  149.05 38.57 180 top
CD110  10U_0402_6.3V6M  [C_0402]  144.57 42.76 90 bottom
CD111  10U_0402_6.3V6M  [C_0402]  129.71 42.2 270 top
CD112  10U_0402_6.3V6M  [C_0402]  131.67 38.69 0 top
CD113  1U_0201_6.3V6K  [C_0201]  144.57 41.11 90 bottom
CD114  1U_0201_6.3V6K  [C_0201]  135.08 46.82 180 top
CD115  0.1U_0201_10V6K  [C_0201]  96.34 46.58 90 top
CE3  2200P_0402_50V7K  [C_0402]  257.09 52.76 270 top
CE4  2200P_0402_50V7K  [C_0402]  254.28 43.48 90 top
CE8  .047U_0402_16V7K  [C_0402]  268.51 50.42 270 top
CE10  1U_0402_6.3V6K  [C_0402]  244.58 75.29 270 top
CE11  0.1U_0201_10V6K  [C_0201]  252.59 66.98 0 top
CE12  1U_0402_6.3V6K  [C_0402]  247.44 74.38 90 top
CE13  0.1U_0201_10V6K  [C_0201]  263.91 52.38 180 top
CE14  1U_0402_6.3V6K  [C_0402]  264.52 63.22 180 bottom
CE15  0.1U_0201_10V6K  [C_0201]  267.43 71.65 90 top
CE16  10U_0603_6.3V6M  [C_0603]  262.35 68.77 90 top
CE17  22U_0603_6.3V6M  [C_0603]  256.33 61.49 270 top
CE18  0.1U_0201_10V6K  [C_0201]  257.22 61.08 270 top
CE19  0.1U_0201_10V6K  [C_0201]  257.22 58.92 270 top
CE20  0.1U_0201_10V6K  [C_0201]  263.91 52.95 180 top
CE21  0.1U_0201_10V6K  [C_0201]  261.59 52.86 270 top
CE22  0.1U_0201_10V6K  [C_0201]  263.26 48.25 0 top
CE23  0.1U_0201_10V6K  [C_0201]  266.79 71.65 90 top
CE24  2200P_0402_50V7K  [C_0402]  263.34 66.86 180 top
CE25  0.1U_0201_10V6K  [C_0201]  271.02 56.09 0 top
CE26  2200P_0402_50V7K  [C_0402]  265.17 66.89 180 top
CE27  2200P_0402_50V7K  [C_0402]  264.96 68.03 180 top
CE28  10P_0402_50V8J  [C_0402]  255.25 68.13 180 top
CE29  10P_0402_50V8J  [C_0402]  256.11 68.13 0 top
CE30  1U_0402_6.3V6K  [C_0402]  276.01 66.3 90 top
CE31  1U_0402_6.3V6K  [C_0402]  257.42 57.11 180 top
CE32  10U_0603_6.3V6M  [C_0603]  176.05 72.09 0 top
CE35  100P_0402_50V8J  [C_0402]  124.25 65.74 270 top
CE36  0.1U_0402_25V6  [C_0402]  257.01 46.78 90 top
CE37  100P_0402_50V8J  [C_0402]  43.02 69.05 0 bottom
CE38  0.1U_0402_25V6  [C_0402]  273.09 63.46 270 top
CE39  100P_0402_50V8J  [C_0402]  83.06 50.6 90 bottom
CE40  4700P_0402_25V7K  [C_0402]  271.11 56.85 0 top
CE46  100P_0402_50V8J  [C_0402]  163.5 41.18 180 bottom
CE47  4700P_0402_25V7K  [C_0402]  269.46 52.84 270 top
CE52  0.1U_0402_25V6K  [C_0402]  254.61 74.11 180 top
CE53  0.1U_0402_25V6K  [C_0402]  262.36 73.84 180 top
CE54  10P_0402_50V8J  [C_0402]  252.84 65.08 180 top
CE57  33P_0402_50V8J  [C_0402]  252.65 58.2 270 top
CE59  12P_0402_50V8J  [C_0402]  259.11 50.49 270 top
CE60  68P_0402_50V8J  [C_0402]  258.22 50.49 270 top
CE61  68P_0402_50V8J  [C_0402]  254.61 73.21 180 top
CE62  4700P_0402_25V7K  [C_0402]  255.19 60.99 270 top
CE63  1U_0402_6.3V6K  [C_0402]  268.65 83.52 90 top
CE64  0.1U_0402_25V6  [C_0402]  262.93 83.31 180 top
CE65  22P_0402_50V8J  [C_0402]  261.79 80.27 90 top
CE66  0.1U_0402_25V6  [C_0402]  170.15 36.43 0 top
CE500  1U_0402_6.3V6K  [C_0402]  251.41 80.43 90 top
CE501  0.1U_0402_25V6K  [C_0402]  260.24 77.57 270 top
CE502  1U_0402_6.3V6K  [C_0402]  252.98 79.46 180 top
CI1  100U_1206_6.3V6M  [C_1206]  14.7 29.4 0 bottom
CI3  0.1U_0201_10V6K  [C_0201]  14.52 26.54 270 bottom
CI4  0.1U_0402_25V6  [C_0402]  17.62 24.22 0 bottom
CI5  0.1U_0402_25V6  [C_0402]  17.62 23.33 0 bottom
CI6  10U_0603_10V6M  [C_0603]  22.48 28.36 0 top
CI7  0.1U_0201_10V6K  [C_0201]  22.93 29.28 0 top
CI13  0.1U_0402_25V6  [C_0402]  276.84 69.14 180 top
CI14  100U_1206_6.3V6M  [C_1206]  288.26 58.73 180 top
CI16  0.1U_0402_25V6  [C_0402]  276.84 68.13 180 top
CI17  0.1U_0201_10V6K  [C_0201]  289.34 58.82 90 top
CI19  0.1U_0201_10V6K  [C_0201]  267.3 75.15 270 top
CI31  10U_0402_6.3V6M  [C_0402]  266.55 74.99 180 top
CI32  150U_B2_6.3VM_R35M  [C_B2]  292.91 58.16 180 top
CI33  47U_0603_6.3V6M  [C_0603]  268.08 77.05 0 top
CI34  47U_0603_6.3V6M  [C_0603]  267.11 76.07 180 top
CI43  12P_0402_50V8J  [C_0402]  290.1 58.4 90 top
CI44  68P_0402_50V8J  [C_0402]  291.05 58.4 90 top
CI45  12P_0402_50V8J  [C_0402]  15.45 30.9 0 bottom
CI46  68P_0402_50V8J  [C_0402]  15.27 26.7 270 bottom
CLP1  -  [EMIST_SUL-12A2M_1P]  35.43 86 270 bottom
CLP2  -  [EMIST_SUL-12A2M_1P]  152.5 29.63 180 bottom
CLP3  -  [EMIST_SUL-12A2M_1P]  28.57 24.6 270 bottom
CLP4  -  [EMIST_SUL-12A2M_1P]  119.5 47.88 180 bottom
CLP5  -  [EMIST_SUL-12A2M_1P]  98.5 88.08 180 bottom
CLP6  -  [EMIST_SUL-12A2M_1P]  76.57 90.5 270 bottom
CLP7  -  [EMIST_SUL-12A2M_1P]  26 30.93 180 bottom
CLP8  -  [EMIST_SUL-12A2M_1P]  103 29.63 180 bottom
CLP9  -  [EMIST_SUL-12A2M_1P]  103 47.88 180 bottom
CLP10  -  [EMIST_SUL-12A2M_1P]  70.5 94.07 180 bottom
CLP11  -  [EMIST_SUL-12A2M_1P]  85 88.08 180 bottom
CLP12  -  [EMIST_SUL-12A2M_1P]  90.3 29.63 180 bottom
CLP13  -  [EMIST_SUL-12A2M_1P]  45.5 92.78 180 bottom
CLP14  -  [EMIST_SUL-12A2M_1P]  53.5 43.53 180 bottom
CLP15  -  [EMIST_SUL-12A2M_1P]  15.42 47 270 bottom
CLP16  -  [EMIST_SUL-12A2M_1P]  19.82 65 270 bottom
CLP17  -  [EMIST_SUL-12A2M_1P]  26 80.08 180 bottom
CLP18  -  [EMIST_SUL-12A2M_1P]  75.3 29.63 180 bottom
CLP19  -  [EMIST_SUL-12A2M_1P]  107.62 52 270 bottom
CLP20  -  [EMIST_SUL-12A2M_1P]  12.2 32.68 180 bottom
CLP21  -  [EMIST_SUL-12A2M_1P]  12.2 16.53 180 bottom
CLP22  -  [EMIST_SUL-12A2M_1P]  289 60.93 0 top
CLP23  -  [EMIST_SUL-12A2M_1P]  285.42 69 90 top
CLP24  -  [EMIST_SUL-12A2M_1P]  12 16.52 0 top
CLP25  -  [EMIST_SUL-12A2M_1P]  289 60.93 180 bottom
CLP26  -  [EMIST_SUL-12A2M_1P]  91.5 47.88 180 bottom
CLP27  -  [EMIST_SUL-12A2M_1P]  119.5 29.63 180 bottom
CLP28  -  [EMIST_SUL-12A2M_1P]  136 29.63 180 bottom
CLP29  -  [EMIST_SUL-12A2M_1P]  160.57 38.4 270 bottom
CLP30  -  [EMIST_SUL-12A2M_1P]  289 77.08 180 bottom
CLP31  -  [EMIST_SUL-12A2M_1P]  289 77.08 0 top
CLP32  -  [EMIST_SUL-12A2M_1P]  12 32.68 0 top
CLP33  -  [EMIST_SUL-12A2M_1P]  15.58 24.6 90 top
CLP34  -  [EMIST_SUL-12A2M_1P]  285.42 69 270 bottom
CLP35  -  [EMIST_SUL-12A2M_1P]  152.5 47.88 180 bottom
CLP36  -  [EMIST_SUL-12A2M_1P]  136 47.88 180 bottom
CLP37  -  [EMIST_SUL-12A2M_1P]  94.82 41 270 bottom
CLP38  -  [EMIST_SUL-12A2M_1P]  61.5 94.07 180 bottom
CMOS1  SHORT PADS~D  [SHORTPADS]  165.27 43.52 0 top
CN60  68P_0402_50V8J  [C_0402]  31.72 15.2 0 top
CN61  0.1U_0201_10V6K  [C_0201]  32 14.47 0 top
CN62  0.1U_0201_10V6K  [C_0201]  17.31 14.4 90 top
CN63  22U_0603_6.3V6M  [C_0603]  31.22 20.02 180 top
CN64  22U_0603_6.3V6M  [C_0603]  27.79 17.36 180 top
CN65  0.22U_0402_10V6K  [C_0402]  31.54 16.77 90 bottom
CN66  0.22U_0402_10V6K  [C_0402]  30.65 16.77 90 bottom
CN67  0.22U_0402_10V6K  [C_0402]  28.87 16.77 90 bottom
CN68  0.22U_0402_10V6K  [C_0402]  27.98 16.77 90 bottom
CN69  0.22U_0402_10V6K  [C_0402]  25.95 16.77 90 bottom
CN70  0.22U_0402_10V6K  [C_0402]  25.06 16.77 90 bottom
CN71  0.22U_0402_10V6K  [C_0402]  23.03 16.77 90 bottom
CN72  0.22U_0402_10V6K  [C_0402]  22.14 16.77 90 bottom
CR1  4.7U_0603_6.3V6K  [C_0603]  274.24 54.63 270 top
CR2  0.1U_0201_10V6K  [C_0201]  275.24 54.89 270 top
CR3  4.7U_0402_6.3V6M  [C_0402]  282.03 62.6 0 top
CR4  0.1U_0201_10V6K  [C_0201]  281.6 61.81 0 top
CR5  4.7U_0603_6.3V6K  [C_0603]  274.35 56.76 180 top
CR6  0.1U_0201_10V6K  [C_0201]  275.17 56.47 90 top
CR8  1U_0402_6.3V6K  [C_0402]  283 61.68 0 top
CR9  4.7U_0402_6.3V6M  [C_0402]  283.44 59 90 top
CR10  0.1U_0201_10V6K  [C_0201]  283.1 58.3 0 top
CR13  0.1U_0402_25V6  [C_0402]  274.15 58.79 0 top
CR14  0.1U_0402_25V6  [C_0402]  274.15 57.84 0 top
CR15  1U_0402_6.3V6K  [C_0402]  281.09 51.39 270 top
CR17  0.1U_0201_10V6K  [C_0201]  284.14 49.65 270 top
CR18  4.7U_0603_6.3V6K  [C_0603]  278.68 51.43 90 top
CR19  0.1U_0201_10V6K  [C_0201]  279.65 53.67 0 top
CR20  4.7U_0603_6.3V6K  [C_0603]  279.94 51.43 90 top
CR21  5P_0402_50V8C  [C_0402]  284.4 53.84 180 top
CR25  12P_0402_50V8J  [C_0402]  280.54 64.35 180 top
CR26  82P_0402_50V8J  [C_0402]  280.54 65.24 180 top
CR29  10U_0402_6.3V6M  [C_0402]  277.63 52.89 270 top
CR30  0.1U_0201_10V6K  [C_0201]  277.69 53.65 180 top
CR31  0.1U_0402_25V6  [C_0402]  274.11 60.71 0 top
CR32  0.1U_0402_25V6  [C_0402]  274.11 59.78 0 top
CT1  0.1U_0201_10V6K  [C_0201]  42.61 81.45 90 bottom
CT2  0.22U_0201_6.3V6K  [C_0201]  38.27 50.76 90 bottom
CT3  0.22U_0201_6.3V6K  [C_0201]  38.9 50.76 90 bottom
CT4  0.22U_0201_6.3V6K  [C_0201]  35.63 50.71 90 bottom
CT5  0.22U_0201_6.3V6K  [C_0201]  36.2 50.71 90 bottom
CT6  0.22U_0201_6.3V6K  [C_0201]  36.92 51.25 270 bottom
CT7  0.22U_0201_6.3V6K  [C_0201]  37.5 51.25 270 bottom
CT8  0.22U_0201_6.3V6K  [C_0201]  34.38 51.25 270 bottom
CT9  0.22U_0201_6.3V6K  [C_0201]  34.96 51.25 270 bottom
CT10  0.1U_0201_10V6K  [C_0201]  40.43 61.08 180 bottom
CT11  0.1U_0201_10V6K  [C_0201]  40.43 60.51 180 bottom
CT12  0.1U_0201_10V6K  [C_0201]  42.96 59.62 180 bottom
CT13  0.1U_0201_10V6K  [C_0201]  42.96 60.19 180 bottom
CT14  0.1U_0201_10V6K  [C_0201]  40.43 58.79 180 bottom
CT15  0.1U_0201_10V6K  [C_0201]  40.43 59.37 180 bottom
CT16  0.1U_0201_10V6K  [C_0201]  42.96 58.41 180 bottom
CT17  0.1U_0201_10V6K  [C_0201]  42.96 57.84 180 bottom
CT18  0.1U_0201_10V6K  [C_0201]  39.92 57.01 180 top
CT19  0.1U_0201_10V6K  [C_0201]  39.92 57.59 180 top
CT20  27P_0402_50V8J  [C_0402]  24.81 50.63 270 bottom
CT21  27P_0402_50V8J  [C_0402]  24.81 51.52 90 bottom
CT25  1U_0201_6.3V6M  [C_0201]  35.22 57.66 270 top
CT26  1U_0201_6.3V6M  [C_0201]  35.84 57.51 0 top
CT27  1U_0201_6.3V6M  [C_0201]  32.06 60.3 180 top
CT28  1U_0201_6.3V6M  [C_0201]  35.22 60.28 90 top
CT29  1U_0201_6.3V6M  [C_0201]  32.67 58.43 0 top
CT30  1U_0201_6.3V6M  [C_0201]  32.03 60.9 180 top
CT31  1U_0201_6.3V6M  [C_0201]  35.81 59.93 0 top
CT32  1U_0201_6.3V6M  [C_0201]  34.74 55.88 270 top
CT33  1U_0201_6.3V6M  [C_0201]  34.8 56.47 0 top
CT34  1U_0201_6.3V6M  [C_0201]  33.19 55.11 270 top
CT35  1U_0201_6.3V6M  [C_0201]  32.13 56.41 270 top
CT36  1U_0201_6.3V6M  [C_0201]  32.55 55.11 270 top
CT37  1U_0201_6.3V6M  [C_0201]  33.24 56.99 90 top
CT38  1U_0201_6.3V6M  [C_0201]  34.74 58.9 180 top
CT39  1U_0201_6.3V6M  [C_0201]  34.12 60.28 180 top
CT40  1U_0201_6.3V6M  [C_0201]  34.12 59.65 180 top
CT41  1U_0201_6.3V6M  [C_0201]  34.56 61.54 0 top
CT42  1U_0201_6.3V6M  [C_0201]  30.8 60.78 90 top
CT43  1U_0201_6.3V6M  [C_0201]  30.2 60.3 180 top
CT44  10U_0402_6.3V6M  [C_0402]  22.9 64.02 90 bottom
CT45  10U_0402_6.3V6M  [C_0402]  21.76 64.02 90 bottom
CT46  10U_0402_6.3V6M  [C_0402]  24.17 64.02 90 bottom
CT47  10U_0402_6.3V6M  [C_0402]  25.44 64.02 90 bottom
CT48  1U_0201_6.3V6M  [C_0201]  30.08 56.93 0 top
CT49  1U_0201_6.3V6M  [C_0201]  29.43 57.59 180 top
CT50  1U_0201_6.3V6M  [C_0201]  29.43 58.25 180 top
CT51  1U_0201_6.3V6M  [C_0201]  29.43 58.88 180 top
CT52  1U_0201_6.3V6M  [C_0201]  29.78 59.64 180 top
CT53  1U_0201_6.3V6M  [C_0201]  32.69 59.06 0 top
CT54  1U_0201_6.3V6M  [C_0201]  29.43 56.95 180 top
CT55  47U_0603_6.3V6M  [C_0603]  23.73 68.67 180 bottom
CT56  47U_0603_6.3V6M  [C_0603]  23.73 67.4 180 bottom
CT57  47U_0603_6.3V6M  [C_0603]  23.73 66.13 180 bottom
CT59  10U_0402_6.3V6M  [C_0402]  30.52 59.57 0 top
CT60  10U_0402_6.3V6M  [C_0402]  31.4 56.37 270 top
CT61  1U_0201_6.3V6M  [C_0201]  30.68 55.75 270 top
CT62  1U_0201_6.3V6M  [C_0201]  30.74 58.21 270 top
CT63  1U_0201_6.3V6M  [C_0201]  32.05 57.63 90 top
CT64  1U_0201_6.3V6M  [C_0201]  31.43 57.63 90 top
CT67  1U_0402_6.3V6K  [C_0402]  34 58.17 270 top
CT68  47U_0603_6.3V6M  [C_0603]  23.54 53.87 90 bottom
CT69  47U_0603_6.3V6M  [C_0603]  22.27 53.87 90 bottom
CT70  .1U_0402_16V7K  [C_0402]  39.25 43.8 0 bottom
CT71  2.2U 16V K X5R 0402  [C_0402]  32.81 69.55 270 bottom
CT72  2.2U 16V K X5R 0402  [C_0402]  34.71 71.46 180 top
CT73  2.2U 16V K X5R 0402  [C_0402]  28.54 71.71 0 top
CT74  1U_0402_16V6K  [C_0402]  34.73 69.23 270 bottom
CT75  22U_0805_25V6M  [C_0805]  30.9 77.94 90 top
CT76  22U_0805_25V6M  [C_0805]  32.68 77.94 90 top
CT77  22U_0805_25V6M  [C_0805]  30.9 76.41 270 top
CT78  22U_0805_25V6M  [C_0805]  32.68 76.41 270 top
CT80  0.1U_0201_10V6K  [C_0201]  23.92 70.32 0 bottom
CT81  0.1U_0201_10V6K  [C_0201]  23.92 70.95 0 bottom
CT82  1U_0603_25V6K  [C_0603]  28.24 78.44 180 bottom
CT83  1U_0402_16V6K  [C_0402]  30.14 69.55 270 bottom
CT84  10U_0603_6.3V6M  [C_0603]  38.02 70.7 180 top
CT85  1000P_0402_50V7K  [C_0402]  24.93 78.57 0 bottom
CT86  1000P_0402_50V7K  [C_0402]  22.65 77.1 90 top
CT87  0.22U_0402_16V7K  [C_0402]  30.96 73.7 0 top
CT88  0.1U_0201_10V6K  [C_0201]  28.95 29.08 270 top
CT89  1U_0402_10V6K  [C_0402]  29.94 29.9 180 top
CT90  1U_0402_6.3V6K  [C_0402]  33.15 30.11 270 top
CT91  2.2U_0402_10V6M  [C_0402]  37.51 29.61 90 top
CT92  0.1U_0402_25V6K  [C_0402]  35.91 24.67 270 top
CT93  1U_0402_10V6K  [C_0402]  28.15 34.79 0 top
CT94  1U_0603_25V6-K~D  [C_0603]  28.22 32.63 90 bottom
CT95  0.22U_0201_6.3V6K  [C_0201]  25.72 58.76 180 bottom
CT96  0.22U_0201_6.3V6K  [C_0201]  25.72 59.4 180 bottom
CT97  0.22U_0201_6.3V6K  [C_0201]  25.72 61.02 180 bottom
CT98  0.22U_0201_6.3V6K  [C_0201]  25.72 60.39 180 bottom
CT99  0.47U_0201_25V  [C_0201]  9.3 81.67 180 bottom
CT100  0.47U_0201_25V  [C_0201]  8.72 83.78 180 bottom
CT101  0.47U_0201_25V  [C_0201]  9.31 84.37 90 bottom
CT102  0.47U_0201_25V  [C_0201]  9.3 81.11 180 bottom
CT123  0.22U_0201_6.3V6K  [C_0201]  33.09 50.71 90 bottom
CT124  0.22U_0201_6.3V6K  [C_0201]  33.66 50.71 90 bottom
CT125  0.22U_0201_6.3V6K  [C_0201]  30.27 50.63 90 bottom
CT126  0.22U_0201_6.3V6K  [C_0201]  30.9 50.63 90 bottom
CT127  0.22U_0201_6.3V6K  [C_0201]  31.72 51.25 270 bottom
CT128  0.22U_0201_6.3V6K  [C_0201]  32.29 51.25 270 bottom
CT129  0.22U_0201_6.3V6K  [C_0201]  28.86 51.24 270 bottom
CT130  0.22U_0201_6.3V6K  [C_0201]  29.43 51.24 270 bottom
CT142  22U_0805_25V6M  [C_0805]  36.62 39.42 270 bottom
CT143  22U_0805_25V6M  [C_0805]  34.83 39.39 270 bottom
CT144  22U_0805_25V6M  [C_0805]  31.27 39.39 270 bottom
CT145  22U_0805_25V6M  [C_0805]  33.05 39.39 270 bottom
CT147  2.2U 16V K X5R 0402  [C_0402]  21.84 43.39 180 bottom
CT148  2.2U 16V K X5R 0402  [C_0402]  23.91 39.5 270 bottom
CT149  2.2U 16V K X5R 0402  [C_0402]  26.59 45.81 180 top
CT150  1U_0402_16V6K  [C_0402]  22.89 39.5 270 bottom
CT151  1U_0603_25V6K  [C_0603]  34.97 44.06 270 top
CT152  1U_0201_6.3V6M  [C_0201]  26.19 45.03 180 top
CT153  10U_0402_6.3V6M  [C_0402]  25.7 44.15 180 top
CT154  820P_0402_50V7K  [C_0402]  31.91 49.03 270 bottom
CT155  820P_0402_50V7K  [C_0402]  29.13 46.31 270 top
CT156  0.1U_0201_10V6K  [C_0201]  22.9 48.13 270 bottom
CT157  0.1U_0201_10V6K  [C_0201]  23.54 48.13 270 bottom
CT158  0.22U_0402_16V7K  [C_0402]  30.12 45.42 90 top
CT159  0.22U_0201_6.3V6K  [C_0201]  25.7 54.82 180 bottom
CT160  0.22U_0201_6.3V6K  [C_0201]  25.7 54.19 180 bottom
CT161  0.22U_0201_6.3V6K  [C_0201]  25.7 55.97 180 bottom
CT162  0.22U_0201_6.3V6K  [C_0201]  25.7 56.6 180 bottom
CT163  0.47U_0201_25V  [C_0201]  8.84 67.14 180 bottom
CT164  0.47U_0201_25V  [C_0201]  8.95 69.25 180 bottom
CT165  0.47U_0201_25V  [C_0201]  9.23 69.81 180 bottom
CT166  0.47U_0201_25V  [C_0201]  9.23 66.56 180 bottom
CT167  1U_0603_25V6-K~D  [C_0603]  32.86 31.42 90 top
CT178  0.1U_0201_10V6K  [C_0201]  39.92 55.94 180 top
CT179  0.1U_0201_10V6K  [C_0201]  40.43 55.37 180 bottom
CT180  0.1U_0201_10V6K  [C_0201]  42.96 55.81 180 bottom
CT181  0.1U_0201_10V6K  [C_0201]  40.36 53.61 180 bottom
CT182  0.1U_0201_10V6K  [C_0201]  40.36 54.18 180 bottom
CT183  0.1U_0201_10V6K  [C_0201]  42.96 56.38 180 bottom
CT184  0.1U_0201_10V6K  [C_0201]  39.92 55.36 180 top
CT185  0.1U_0201_10V6K  [C_0201]  40.43 55.94 180 bottom
CT186  0.1U_0201_10V6K  [C_0201]  40.43 57.02 180 bottom
CT187  0.1U_0201_10V6K  [C_0201]  40.43 57.59 180 bottom
CT189  12P_0402_50V8J  [C_0402]  15.33 81.62 0 top
CT190  82P_0402_50V8J  [C_0402]  15.33 80.73 0 top
CT191  12P_0402_50V8J  [C_0402]  15.33 66.76 0 top
CT192  82P_0402_50V8J  [C_0402]  15.33 65.74 0 top
CT201  1P_0201_50V8C  [C_0201]  35.16 66.99 180 bottom
CT202  1P_0201_50V8C  [C_0201]  34.21 65.87 180 bottom
CT203  1P_0201_50V8C  [C_0201]  33.28 66.99 180 bottom
CT204  1P_0201_50V8C  [C_0201]  32.61 65.79 180 bottom
CT205  0.1U_0402_25V6  [C_0402]  32.94 78.65 270 bottom
CT237  0.1U_0402_25V6  [C_0402]  26.26 26.36 90 bottom
CT238  0.1U_0402_25V6  [C_0402]  3.94 10.28 270 bottom
CV1  0.1U_0402_25V6  [C_0402]  216.12 35.6 90 bottom
CV2  0.1U_0402_25V6  [C_0402]  215.1 35.6 90 bottom
CV3  0.1U_0402_25V6  [C_0402]  214.09 35.6 90 bottom
CV4  0.1U_0402_25V6  [C_0402]  213.07 35.6 90 bottom
CV5  0.1U_0402_25V6  [C_0402]  212.06 35.6 90 bottom
CV6  0.1U_0402_25V6  [C_0402]  211.04 35.6 90 bottom
CV7  0.1U_0402_25V6  [C_0402]  210.02 35.6 90 bottom
CV8  0.1U_0402_25V6  [C_0402]  209.01 35.6 90 bottom
CV9  0.1U_0402_25V6  [C_0402]  207.99 35.6 90 bottom
CV10  0.1U_0402_25V6  [C_0402]  206.98 35.6 90 bottom
CV11  0.1U_0603_50V7K  [C_0603]  222.41 35.62 0 bottom
CV12  0.1U_0201_10V6K  [C_0201]  217.98 36.66 180 bottom
CV13  1000P_0402_50V7K  [C_0402]  225.94 31.62 0 bottom
CV14  0.01U_0402_50V7K  [C_0402]  225.95 30.7 0 bottom
CV15  0.1U_0603_50V7K  [C_0603]  222.41 34.35 0 bottom
CV16  10U_0603_10V6M  [C_0603]  228.01 26.5 0 bottom
CV17  0.01UF_0402_25V7K  [C_0402]  231.92 30.65 0 top
CV18  12P_0402_50V8J  [C_0402]  185.22 38.53 270 bottom
CV19  82P_0402_50V8J  [C_0402]  186.12 38.53 270 bottom
CV20  12P_0402_50V8J  [C_0402]  218.01 35.74 180 bottom
CV21  82P_0402_50V8J  [C_0402]  218.01 34.73 180 bottom
CV22  12P_0402_50V8J  [C_0402]  225.77 36.14 270 top
CV23  82P_0402_50V8J  [C_0402]  226.66 36.14 270 top
CV24  12P_0402_50V8J  [C_0402]  223.36 38.14 90 top
CV25  82P_0402_50V8J  [C_0402]  222.34 38.14 90 top
CV31  0.1U_0201_25V6K  [C_0201]  21.76 41.65 180 top
CV32  0.1U_0201_25V6K  [C_0201]  21.76 42.66 180 top
CV33  0.1U_0201_25V6K  [C_0201]  21.76 43.68 180 top
CV34  0.1U_0201_25V6K  [C_0201]  21.76 44.7 180 top
CV35  0.1U_0201_25V6K  [C_0201]  21.14 45.91 180 top
CV36  0.1U_0201_25V6K  [C_0201]  21.14 46.54 180 top
CV37  0.1U_0201_25V6K  [C_0201]  21.16 47.96 180 top
CV38  0.1U_0201_25V6K  [C_0201]  21.16 48.6 180 top
CV39  0.1U_0201_10V6K  [C_0201]  20.24 55.62 270 bottom
CV40  0.1U_0201_10V6K  [C_0201]  15.21 50.98 270 top
CV41  10U_0402_10V6M  [C_0402]  16.22 51.14 270 top
CV54  33P_0402_50V8J  [C_0402]  190.25 38.51 180 bottom
CV55  33P_0402_50V8J  [C_0402]  191.13 38.44 0 bottom
CZ1  0.1U_0201_10V6K  [C_0201]  227.28 36.63 0 bottom
CZ2  0.1U_0201_10V6K  [C_0201]  186.96 38.54 270 bottom
CZ3  100P_0402_50V8J  [C_0402]  170.5 47.24 90 bottom
CZ10  0.1U_0402_25V6  [C_0402]  226.08 75.94 0 top
CZ11  0.1U_0402_25V6  [C_0402]  226.08 76.89 0 top
CZ12  0.1U_0402_25V6  [C_0402]  237.61 50.38 0 bottom
CZ13  0.1U_0402_25V6  [C_0402]  237.61 49.49 0 bottom
CZ17  .047U_0402_16V7K  [C_0402]  229.91 88.6 90 top
CZ18  .047U_0402_16V7K  [C_0402]  228.13 88.6 90 top
CZ19  33P_0402_50V8J  [C_0402]  229.96 66.2 270 top
CZ20  22U_0603_6.3V6M  [C_0603]  228.9 66.19 270 top
CZ21  33P_0402_50V8J  [C_0402]  230.89 66.24 270 top
CZ23  47P_0402_50V8J  [C_0402]  227.25 88.6 90 top
CZ24  100P_0402_50V8J  [C_0402]  229.53 71.38 90 top
CZ25  2200P_0402_50V7K  [C_0402]  229.02 88.6 90 top
CZ26  100U_B2_6.3VM_R35M  [C_B2]  239.44 61.55 180 bottom
CZ27  10U_0402_6.3V6M  [C_0402]  241.05 57.34 90 top
CZ28  0.01UF_0402_25V7K  [C_0402]  240.01 57.46 180 top
CZ29  0.01UF_0402_25V7K  [C_0402]  240.01 56.57 180 top
CZ30  0.1U_0201_10V6K  [C_0201]  240.25 54.71 180 top
CZ31  0.1U_0201_10V6K  [C_0201]  240.86 36.23 270 top
CZ32  4.7U_0603_6.3V6K  [C_0603]  237.27 36.31 270 top
CZ33  15P_0402_50V8J  [C_0402]  240.01 55.68 180 top
CZ34  2.2P_0402_50V8C  [C_0402]  240.12 36.41 270 top
CZ35  12P_0402_50V8J  [C_0402]  239.23 36.39 270 top
CZ36  15P_0402_50V8J  [C_0402]  238.34 36.39 270 top
CZ37  4.7U_0402_6.3V6M  [C_0402]  281.98 57.79 90 bottom
CZ38  47P_0402_50V8J  [C_0402]  280.21 44.61 270 bottom
CZ39  33P_0402_50V8J  [C_0402]  284.02 57.67 90 bottom
CZ40  33P_0402_50V8J  [C_0402]  280.15 51.42 180 bottom
CZ41  0.1U_0402_25V6  [C_0402]  281.09 57.79 90 bottom
CZ50  0.1U_0201_10V6K  [C_0201]  166.26 38.25 180 bottom
CZ51  0.1U_0201_10V6K  [C_0201]  169.91 37.83 0 bottom
CZ52  10U_0603_10V6M  [C_0603]  170.07 36.88 0 bottom
CZ53  0.1U_0201_10V6K  [C_0201]  163.53 43.8 180 bottom
CZ54  0.1U_0201_10V6K  [C_0201]  169.71 46.4 90 bottom
CZ55  10U_0603_10V6M  [C_0603]  166.11 50.86 180 bottom
CZ56  0.1U_0402_25V6  [C_0402]  164.57 49.44 270 bottom
CZ57  12P_0402_50V8J  [C_0402]  178.94 34.25 180 top
CZ58  68P_0402_50V8J  [C_0402]  178.94 35.14 180 top
CZ59  12P_0201_50V8J  [C_0201]  167.07 49.69 180 bottom
CZ60  68P_0201_50V8J  [C_0201]  167.09 49.11 180 bottom
CZ61  .047U_0402_16V7K  [C_0402]  189.41 40.07 270 top
CZ62  68P_0402_50V8J  [C_0402]  197.01 36.96 270 top
CZ63  68P_0402_50V8J  [C_0402]  195.99 36.96 270 top
CZ64  0.1U_0201_10V6K  [C_0201]  193.58 38.18 90 top
CZ66  0.1U_0201_10V6K  [C_0201]  192.31 38.18 90 top
CZ67  0.1U_0201_10V6K  [C_0201]  192.94 38.18 90 top
CZ68  0.1U_0201_10V6K  [C_0201]  194.21 38.18 90 top
CZ69  68P_0402_50V8J  [C_0402]  194.59 36.96 270 top
CZ71  68P_0402_50V8J  [C_0402]  192.56 36.96 270 top
CZ72  68P_0402_50V8J  [C_0402]  193.58 36.96 270 top
CZ73  68P_0402_50V8J  [C_0402]  195.04 38.33 90 top
CZ75  4.7U_0402_6.3V6M  [C_0402]  163.5 42.15 180 bottom
CZ78  100P_0402_50V8J  [C_0402]  202.72 36.42 270 bottom
CZ80  10P_0402_50V8J  [C_0402]  177.26 36.18 90 top
CZ81  10P_0402_50V8J  [C_0402]  177.08 35.09 270 top
CZ82  0.1U_0201_10V6K  [C_0201]  163.59 48.41 180 bottom
CZ83  68P_0402_50V8J  [C_0402]  175.18 36.6 90 bottom
